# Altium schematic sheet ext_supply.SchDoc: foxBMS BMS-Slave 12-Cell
size A3; DocumentNumber: 11; SheetNumber: 11; SheetTotal: 15; AUTHOR: Fraunhofer IISB foxBMS Team; SheetDescription: External Power Supply
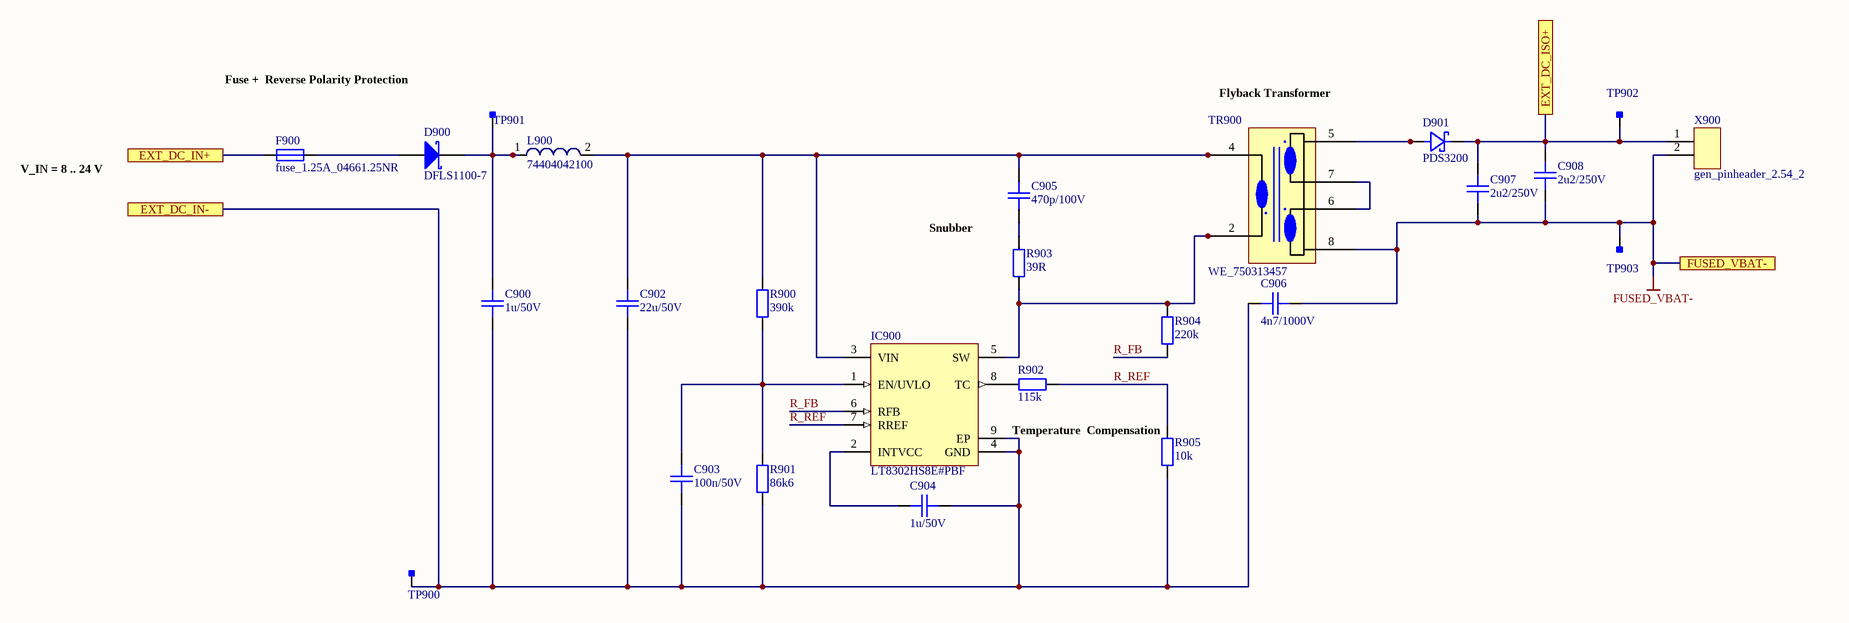
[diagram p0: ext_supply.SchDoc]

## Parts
C900  1u/50V  [CAPC2012X14N]
C902  22u/50V  [CAPC2220(5750)230_N]
C903  100n/50V  [CAPC1608X08N]
C904  1u/50V  [CAPC2012X14N]
C905  470p/100V  [CAPC2012X14N]
C906  4n7/1000V  [CAPC4532X16N]
C907  2u2/250V  [CAPC2220(5750)230_N]
C908  2u2/250V  [CAPC2220(5750)230_N]
D900  DFLS1100-7  [DIOD-POWERDI123-2_V]
D901  PDS3200  [PowerDI5]
F900  fuse_1.25A_04661.25NR  [LITTLEFUSE_466]
IC900  LT8302HS8E#PBF  [LT-S8E-8_V]
L900  74404042100  [WE-LQS 4018]
R900  390k  [RESC1608X05N]
R901  86k6  [RESC1608X05N]
R902  115k  [RESC1608X05N]
R903  39R  [RESC2012X05N]
R904  220k  [RESC1608X05N]
R905  10k  [RESC1608X05N]
TP900  Testpoint_Square  [Testpoint_S1]  (value not drawn)  (no BOM)
TP901  Testpoint_Square  [Testpoint_S1]  (value not drawn)  (no BOM)
TP902  Testpoint_Square  [Testpoint_S1]  (value not drawn)  (no BOM)
TP903  Testpoint_Square  [Testpoint_S1]  (value not drawn)  (no BOM)
TR900  WE_750313457  [WE_750313457]
X900  gen_pinheader_2.54_2  [Pinheader_2.54_2]

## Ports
EXT_DC_IN+, EXT_DC_IN-, EXT_DC_ISO+, FUSED_VBAT-

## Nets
FUSED_VBAT-: C906.2 C907.1 C908.1 TP903.1 TR900.8 X900.2 ; port FUSED_VBAT-
EXT_DC_IN+: F900.1 ; port EXT_DC_IN+
EXT_DC_IN-: C900.1 C902.1 C903.1 C904.1 C906.1 IC900.4(GND) IC900.9(EP) R901.1 R905.1 TP900.1 ; port EXT_DC_IN-
EXT_DC_ISO+: C907.2 C908.2 D901.1(C) TP902.1 X900.1 ; port EXT_DC_ISO+
R_FB: IC900.6(RFB) R904.1
R_REF: IC900.7(RREF) R902.2 R905.2
NetC900_2: C900.2 D900.2(K) L900.1 TP901.1
NetC902_2: C902.2 C905.2 IC900.3(VIN) L900.2 R900.2 TR900.3 TR900.4
NetC903_2: C903.2 IC900.1(EN/UVLO) R900.1 R901.2
NetC904_2: C904.2 IC900.2(INTVCC)
NetC905_1: C905.1 R903.2
NetD900_1: D900.1(A) F900.2
NetD901_2: D901.2(A) D901.3(A) TR900.5
NetIC900_5: IC900.5(SW) R903.1 R904.2 TR900.1 TR900.2
NetIC900_8: IC900.8(TC) R902.1
NetTR900_6: TR900.6 TR900.7

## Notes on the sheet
- Fuse +
  Reverse Polarity Protection
- (near TR900) Flyback Transformer
- V_IN = 8 .. 24 V
- Snubber
- (near R905) Temperature
  Compensation

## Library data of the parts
C900 C904 = gen_C_ceramic_1u_50V_X7R_0805: MLCC; Capacitance: 1u; Rated Voltage: 50V; Dielectric: X7R; Case EIA: 0805; Case Metric: 2012; Automotive Qualified: True; Tolerance: ± 10%; AVT Set: x
C902 = gen_C_ceramic_22u_50V_X7R_2220_stacked: MLCC; Capacitance: 22u; Rated Voltage: 50V; Dielectric: X7R; Case EIA: 2220; Case Metric: 5750; Automotive Qualified: True
C903 = gen_C_ceramic_100n_50V_X7R_0603: MLCC; Capacitance: 100n; Rated Voltage: 50V; Dielectric: X7R; Case EIA: 0603; Case Metric: 1608; PnP Package: C_0603_10; PnP Value: 100n/50V/X7R; PnP equipped: x; Automotive Qualified: True
C905 = gen_C_ceramic_470p_100V_X7R_0805: MLCC; Capacitance: 470p; Rated Voltage: 100V; Dielectric: X7R; Case EIA: 0805; Case Metric: 2012; Automotive Qualified: True
C906 = gen_C_ceramic_4n7_1000V_X7R_1812: MLCC; Capacitance: 4n7; Rated Voltage: 1000V; Dielectric: X7R; Case EIA: 1812; Case Metric: 4532; Automotive Qualified: True
C907 C908 = gen_C_ceramic_2u2_250V_X7R_2220: MLCC; Capacitance: 2u2; Rated Voltage: 250V; Dielectric: X7R; Case EIA: 2220; Case Metric: 5750; Automotive Qualified: True
D900 = CMP-2000-05099-1: 1 A High Voltage Schottky Barrier Rectifier, 0.62 V, -55 to 175 degC, 2- Pin POWERDI123, Pb-Free, Tape and Reel; Manufacturer: Diodes Inc; Average Rectified Current-Max: 1A; Peak Current-Max: 40A; Forward Voltage: 0.77V; Reverse Current-Max: 1µA; Reverse Voltage-Max [Vrrm]: 100V
D901 = PDS3200-13: Schottky Diode 3A 200V 780mV; Manufacturer: DIODES Inc; Automotive Qualified: True
F900 = fuse_1.25A_04661.25NR: Fuse, Surface Mount, 466 Series, 1.25 A, 63 VAC, 63 VDC, Very Fast Acting, 1206; Manufacturer: Littlefuse; Automotive Qualified: False
IC900 = CMP-0492-02715-1: Micropower No-Opto Isolated Flyback Converter, 2.8 to 42 V, -40 to 150 degC, 8-Pin SOIC (S8E), RoHS, Tube; PartNumber: LT8302; Output Current: 3.6 A; Number of Outputs: 1; VIN Min: 2.8 V; VIN Max: 42 V
L900 = CMP-1354-00028-1: WE-LQS SMD Power Inductor, L=10 µH; Manufacturer: Wuerth Elektronik; Inductance: 10 ÂµH
R900 = gen_R_390k_0603: SMD Resistor 390k 0603; Tolerance: 1%; Power: 0.1W; Case EIA: 0603; Case Metric: 1608; Maximum Working Voltage: 75V; PnP Package: R_0603; Automotive Qualified: True
R901 = gen_R_86k6_0603: SMD Resistor 86k6 0603; Tolerance: 1%; Power: 0.1W; Case EIA: 0603; Case Metric: 1608; Maximum Working Voltage: 75V; PnP Package: R_0603; Automotive Qualified: True
R902 = gen_R_115k_0603: SMD Resistor 115k 0603; Tolerance: 1%; Power: 0.1W; Case EIA: 0603; Case Metric: 1608; Maximum Working Voltage: 75V; PnP Package: R_0603; Automotive Qualified: True
R903 = gen_R_39R_0805: SMD Resistor 39R 0805; Tolerance: 1%; Power: 0.125W; Case EIA: 0805; Case Metric: 2012; Maximum Working Voltage: 150V; PnP Package: R_0805; Automotive Qualified: True
R904 = gen_R_220k_0603: SMD Resistor 220k 0603; Tolerance: 1%; Power: 0.1W; Case EIA: 0603; Case Metric: 1608; Maximum Working Voltage: 75V; PnP Package: R_0603; Automotive Qualified: False
R905 = gen_R_10k_0603: SMD Resistor 10k 0603; Tolerance: 1%; Power: 0.1W; Case EIA: 0603; Case Metric: 1608; Maximum Working Voltage: 75V; PnP Package: R_0603; Automotive Qualified: True
TP900-TP903 = Testpoint_Square: Testpoint, square
TR900 = WE_750313457: MID-FLYLT Flyback Transformers for Linear Technology; Manufacturer: Würth Elektronik; Automotive Qualified: False
X900 = gen_pinheader_2.54_2: Standard Pinheader, THD, gerade, 2.54mm; Circuits: 2; Rated Voltage: 250V; Rated Current: 3A; Automotive Qualified: False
